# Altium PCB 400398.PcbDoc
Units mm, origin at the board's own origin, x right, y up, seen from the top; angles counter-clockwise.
Board outline 12 x 15.3 mm, 2 copper layers (Top Layer, Bottom Layer), stack 1.001 mm thick; 1 components, 5 nets, 20 pads, 4 vias.
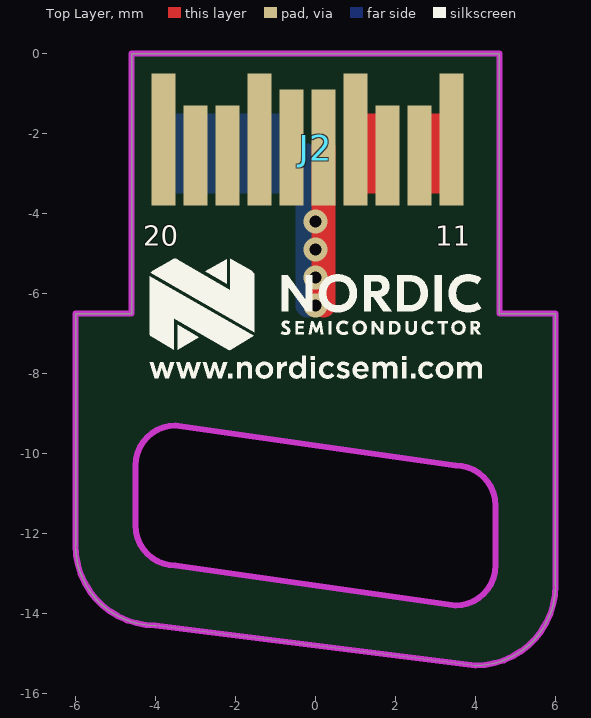
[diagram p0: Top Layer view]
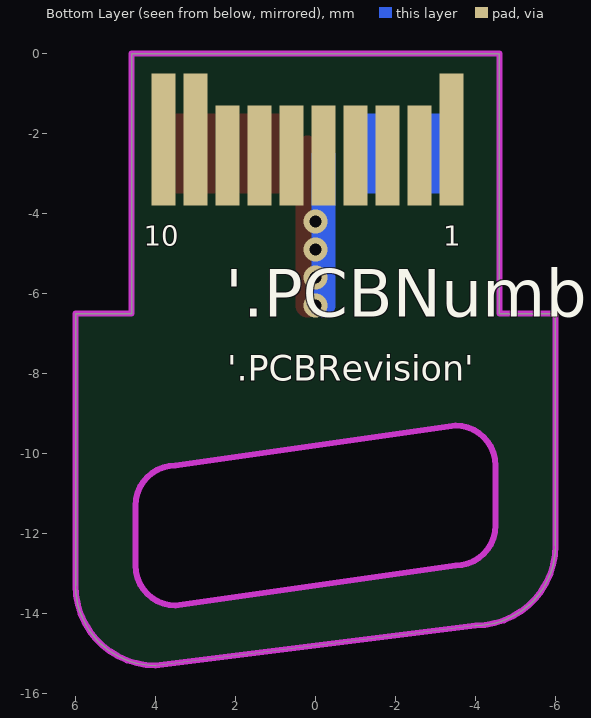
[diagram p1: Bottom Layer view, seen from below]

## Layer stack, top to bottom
Top Solder: solder mask 0.0102, Solder Resist, Dk 3.5
Top Layer: signal copper 0.0356
Dielectric1: core 0.93, FR-4, Dk 4.8
Bottom Layer: signal copper 0.0356
Bottom Solder: solder mask 0.0102, Solder Resist, Dk 3.5

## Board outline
-6,-12.3 -6,-6.5 -4.6,-6.5 -4.6,0 4.6,0 4.6,-6.5 6,-6.5 6,-13.3 cw(c4,-13.3) 4,-15.3 -4,-14.3 cw(c-4,-12.3)
cut-out: -4.5,-11.8 -4.5,-10.3 cw(c-3.5,-10.3) -3.5,-9.3 3.5,-10.3 cw(c3.5,-11.3) 4.5,-11.3 4.5,-12.8 cw(c3.5,-12.8) 3.5,-13.8 -3.5,-12.8 cw(c-3.5,-11.8)
cut-out: -0.6,-9.714

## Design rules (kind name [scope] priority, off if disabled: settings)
Clearance ANT_Clerance [InNet('ANT')] p1: gap=0.127 ignorepadtopadclearanceinfootprint=FALSE except(0: Arc-Hole Track-Hole SMDPad-Hole THPad-Hole Via-Hole Fill-Hole Poly-Hole Region-Hole Text-Hole)
Clearance Polygon_Clearance [(InNamedPolygon('Top_Layer-GND')) or (InNamedPolygon('Bottom_Layer-GND'))] p2: gap=0.254 ignorepadtopadclearanceinfootprint=FALSE except(0: Arc-Hole Track-Hole SMDPad-Hole THPad-Hole Via-Hole Fill-Hole Poly-Hole Region-Hole Text-Hole)
Clearance [All] p3: gap=0.152 ignorepadtopadclearanceinfootprint=FALSE except(0: Arc-Hole Track-Hole SMDPad-Hole THPad-Hole Via-Hole Fill-Hole Poly-Hole Region-Hole Text-Hole)
ComponentClearance [All] p1 off: gap=0.254 collisioncheckmode=3 verticalgap=0.254 showdistances=FALSE
DiffPairsRouting [All] p1: maxlimit=0.15 minlimit=0.15 mostfreqgap=0.15 toplayer_minwidth=0.381 toplayer_maxwidth=0.381 toplayer_prefwidth=0.381 bottomlayer_minwidth=0.381 bottomlayer_maxwidth=0.381 bottomlayer_prefwidth=0.381 maxuncoupledlength=12.7
FabricationTestPointUsage TestPointUsage [All] p1: valid=0 allowmultiple=FALSE
FabricationTestpoint Testpoint [All] p1: side=3 testpointundercomponent=TRUE minsize=1.016 maxsize=2.54 preferedsize=1.524 minholesize=0 maxholesize=1.016 preferedholesize=0.813 testpointgrid=0.025 allowsidetop=TRUE allowsidebottom=TRUE usegrid=TRUE gridtolerance=0
Height [All] p1 off: minheight=0 maxheight=25.4 prefheight=12.7
HoleSize [All] p1: absolutevalues=TRUE maxlimit=5 minlimit=0.305 maxpercent=80.000 minpercent=20.000
MinimumAnnularRing [All] p1 off: minimumring=0.152
PolygonConnect PolygonConnect_1 [isVia and innet(gnd)] p1: connectstyle=Direct reliefconductorwidth=0.254 reliefentries=4 polygonreliefangle="90 Angle" airgapwidth=0.254
PolygonConnect [All] p2: connectstyle=Relief reliefconductorwidth=0.254 reliefentries=4 polygonreliefangle="90 Angle" airgapwidth=0.254
RoutingVias [All] p1: holewidth=0.305 width=0.61 viastyle="Through Hole" minholewidth=0.305 minwidth=0.61 maxholewidth=0.305 maxwidth=0.61
SilkToSolderMaskClearance SilkscreenOverComponentPads [IsPad] p1: minsilkscreentomaskgap=0.254 clearancetoexposedcopper=TRUE
SolderMaskExpansion [All] p1: expansion=0.076
Width [All] p1: maxlimit=2.54 minlimit=0.203 preferedwidth=0.381
23 further rules are at their usual default settings.

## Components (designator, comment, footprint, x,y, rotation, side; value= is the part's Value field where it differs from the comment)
J2 "Card Edge, 0.8mm" "10056847-101LF Mating Board" 0,0 r0 top locked

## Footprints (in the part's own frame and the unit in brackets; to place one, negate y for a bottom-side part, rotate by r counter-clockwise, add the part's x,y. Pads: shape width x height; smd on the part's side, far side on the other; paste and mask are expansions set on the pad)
"10056847-101LF Mating Board" [mm]
  rect 0.6x3.3 smd far side paste-1 mask+0.025: 1(-3.4,-2.15) 9(3,-2.15) 10(3.8,-2.15)
  rect 0.6x2.5 smd far side paste-1 mask+0.025: 2(-2.6,-2.55) 3(-1.8,-2.55) 4(-1,-2.55) 5(-0.2,-2.55) 6(0.6,-2.55) 7(1.4,-2.55) 8(2.2,-2.55)
  rect 0.6x3.3 smd paste-1 mask+0.025: 11(3.4,-2.15) 14(1,-2.15) 17(-1.4,-2.15) 20(-3.8,-2.15)
  rect 0.6x2.5 smd paste-1 mask+0.025: 12(2.6,-2.55) 13(1.8,-2.55) 18(-2.2,-2.55) 19(-3,-2.55)
  rect 0.6x2.9 smd paste-1 mask+0.025: 15(0.2,-2.35) 16(-0.6,-2.35)

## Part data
J2: library part "10056847-101LF Mating Board", "0.8mm pitch, dual edge, card edge connector"

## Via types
v1: diameter 0.61, hole 0.305, Top Layer to Bottom Layer, tented both sides, 4 vias

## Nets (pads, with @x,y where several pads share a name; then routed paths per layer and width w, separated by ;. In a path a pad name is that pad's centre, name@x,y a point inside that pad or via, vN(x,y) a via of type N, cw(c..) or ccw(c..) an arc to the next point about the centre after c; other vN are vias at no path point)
NetJ2_1: J2.1 J2.2
NetJ2_3: J2.3 J2.4
NetJ2_5: J2.5 J2.15 | length 7.7
  Top Layer w0.6: v1@0.2,-6.3 J2.15
  Bottom Layer w0.6: v1@-0.2,-6.3 J2.5
  other v1: 0,-6.3 0,-5.6 0,-4.9 0,-4.2
NetJ2_11: J2.11 J2.12
NetJ2_13: J2.13 J2.14
pads on no net: J2.6 J2.7 J2.8 J2.9 J2.10 J2.16 J2.17 J2.18 J2.19 J2.20

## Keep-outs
Keep-Out Layer:
  lines w0.152: -6,-12.3 ccw(c-4,-12.3) -4,-14.3 4,-15.3 ccw(c4,-13.3) 6,-13.3 6,-6.5 4.6,-6.5 4.6,0 -4.6,0 -4.6,-6.5 -6,-6.5 -6,-12.3 ; -4.5,-11.8 ccw(c-3.5,-11.8) -3.5,-12.8 3.5,-13.8 ccw(c3.5,-12.8) 4.5,-12.8 4.5,-11.3 ccw(c3.5,-11.3) 3.5,-10.3 -3.5,-9.3 ccw(c-3.5,-10.3) -4.5,-10.3 -4.5,-11.8

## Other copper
Top Layer:
  region net NetJ2_13: 1.9,-1.5 0.9,-1.5 0.9,-3.5 1.9,-3.5
  rectangle net NetJ2_11: 2.5,-3.5 3.5,-1.5
Bottom Layer:
  region net NetJ2_1: -2.5,-1.5 -3.5,-1.5 -3.5,-3.5 -2.5,-3.5
  rectangle net NetJ2_3: -1.9,-3.5 -0.9,-1.5

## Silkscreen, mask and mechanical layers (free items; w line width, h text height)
Top Overlay:
  drawing of 43 lines, arcs and shapes, not listed
Bottom Overlay:
  text "'.PCBNumber'" at 2.252,-6.964 h2.03
  text "'.PCBRevision'" at 2.201,-8.183 h0.64
Board Outline:
  lines w0.152: -4.6,-6.5 -6,-6.5 -6,-12.3 ccw(c-4,-12.3) -4,-14.3 4,-15.3 ccw(c4,-13.3) 6,-13.3 6,-6.5 4.6,-6.5 ; -4.5,-11.8 ccw(c-3.5,-11.8) -3.5,-12.8 3.5,-13.8 ccw(c3.5,-12.8) 4.5,-12.8 4.5,-11.3 ccw(c3.5,-11.3) 3.5,-10.3 -3.5,-9.3 ccw(c-3.5,-10.3) -4.5,-10.3 -4.5,-11.8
